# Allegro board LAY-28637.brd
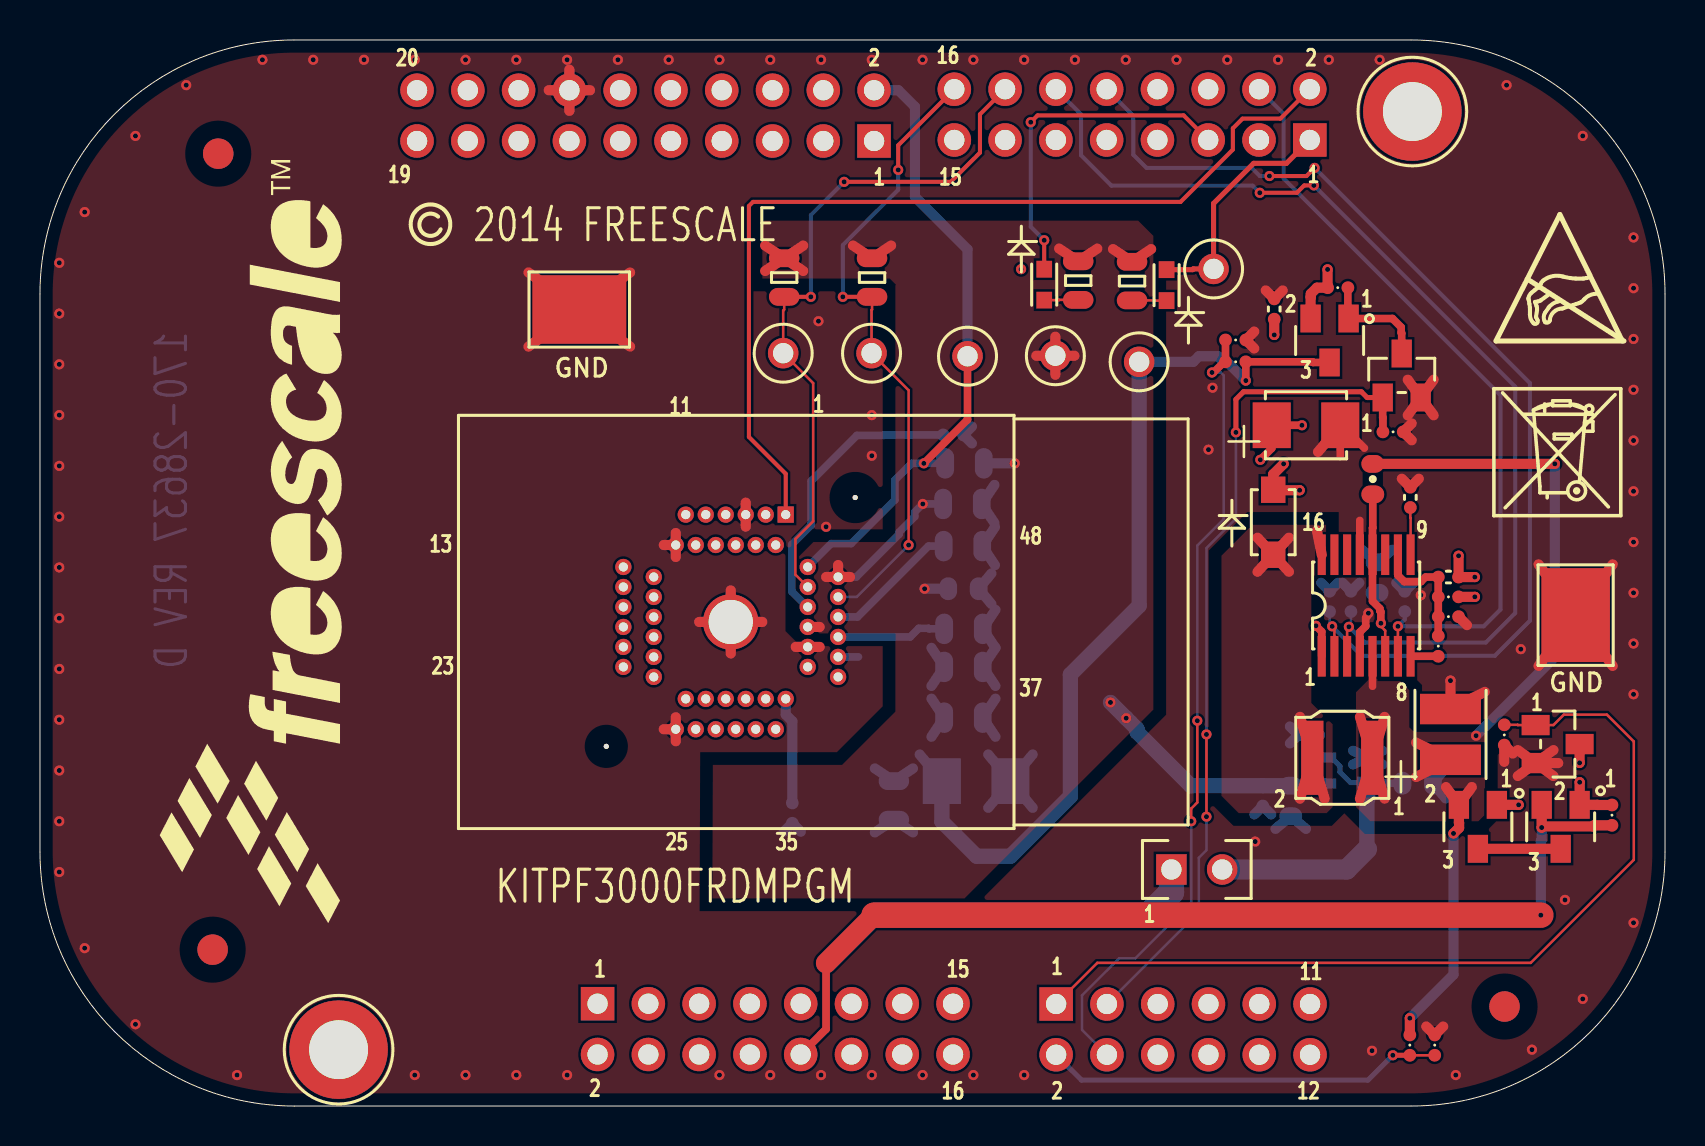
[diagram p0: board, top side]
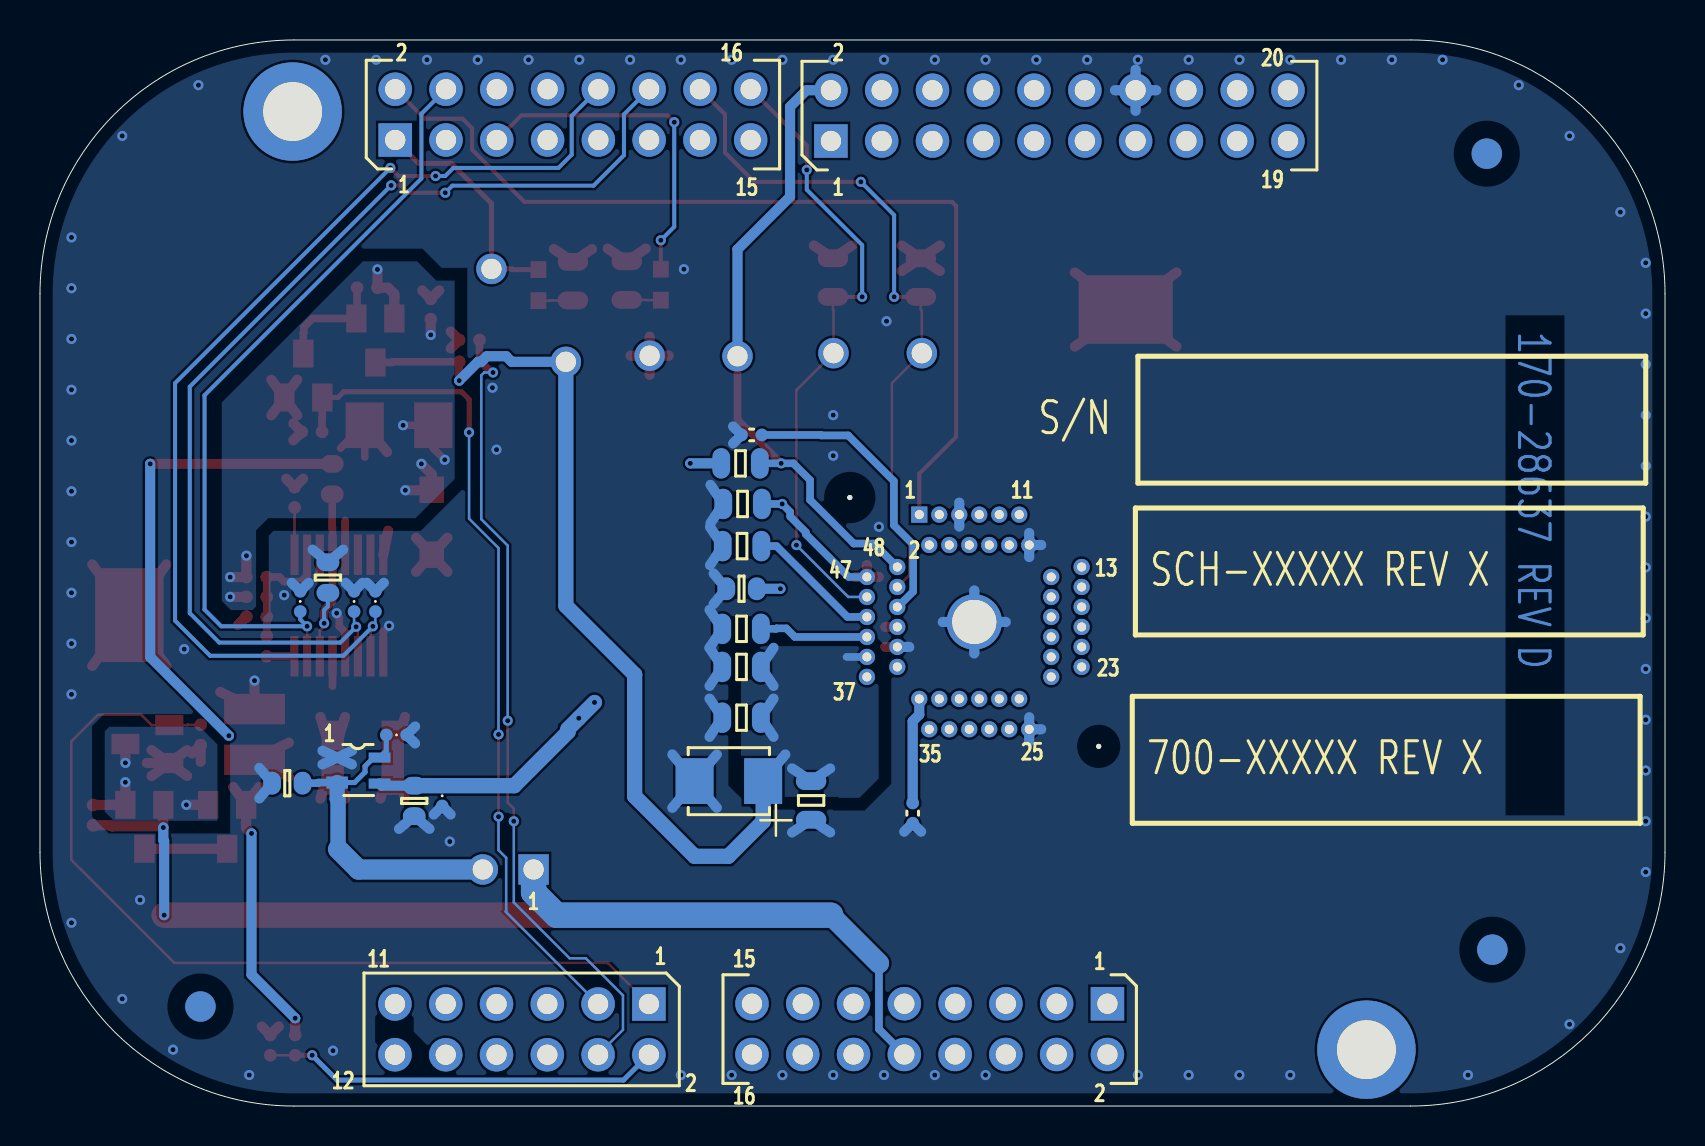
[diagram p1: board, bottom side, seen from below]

Outline 81.28 x 53.34 mm; copper layers: TOP, BOTTOM. Coordinates in mm from the lower left corner of the outline.
Outline path: 0,40.64 arc(3.72,49.62) 12.7,53.34 68.58,53.34 arc(77.56,49.62) 81.28,40.64 81.28,12.7 arc(77.56,3.72) 68.58,0 12.73,0 arc(3.74,3.72) 0,12.7 0,40.64

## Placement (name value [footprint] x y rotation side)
C1  0.1uF  [CC0402_25]  61.73 39.88 90 top
C2  4.7uF  [CC3528-21]  63.32 34.06 0 top
C3  0.1uF  [CC0402_25]  68.54 30.45 90 top
C4  22PF  [CC0402_25]  70.45 26.47 180 top
C5  15UF  [CASE_B]  70.55 18.59 90 top
C6  0.22uF  [CC0402_25]  45.68 33.58 0 bottom
C7  0.1UF  [CC0805_OV]  46.14 30.12 0 bottom
C8  1uF  [CC0805_OV]  46.16 28.02 0 bottom
C9  1.0UF  [CC0603_OV]  46.19 25.88 0 bottom
C10  1uF  [CC0805_OV]  46.19 23.88 0 bottom
C11  1UF  [CC0603_OV]  66.88 26.44 90 bottom
C12  10uF  [CC0805_OV]  46.19 21.97 0 bottom
C13  10uF  [CC3528-21]  46.82 16.26 0 bottom
C14  10uF  [CC0805_OV]  42.71 15.29 270 bottom
C15  0.22uF  [CC0402_25]  37.63 14.66 270 bottom
C16  1.0UF  [CC0603_OV]  62.56 15.27 270 bottom
C17  1.0UF  [CC0603_OV]  68.91 16.15 0 bottom
D1  LED Green  [LED_0603]  50.23 41.1 90 top
D2  LED Red  [LED_0603]  56.35 41.07 90 top
D3  MBR130LSFT1G  [SOD-123]  61.68 29.21 90 top
J1  HDR_2X8  [HDR208]  63.51 48.34 90 bottom
J2  HDR_10X2  [HDR210]  41.72 48.29 90 bottom
J3  HDR_2X8  [HDR208]  27.89 5.12 270 bottom
J4  HDR_2X6  [HDR206]  50.83 5.11 270 bottom
J9  HDR 1X2 TH  [HDR102]  56.59 11.84 90 top
L1  22uH  [IND2_4P3X4P3]  65.14 17.42 180 top
MH1  SMTSO-M1.6-2.25ET  [MH194-116T]  68.64 49.76 0 top
MH2  SMTSO-M1.6-2.25ET  [MH194-116T]  14.94 2.82 0 top
NOREF  -  [unnamed]  8.92 47.65 0 top
NOREF#2  -  [#2]  14.94 2.82 0 top
NOREF#3  -  [#2]  14.4 9.14 90 top
NOREF#4  -  [#2]  -403.54 -384.3 0 top
NOREF#5  -  [#2]  72.72 29.54 0 top
NOREF#6  -  [unnamed]  8.64 7.82 0 top
NOREF#7  -  [#2]  18.16 13.03 0 top
NOREF#8  -  [#2]  -5.22 -35.53 0 top
NOREF#9  -  [#2]  14.94 2.82 0 top
NOREF#10  -  [#2]  -377.51 140.84 0 top
NOREF#11  -  [#2]  19.66 44.25 0 top
NOREF#12  -  [#2]  14.94 2.82 0 top
NOREF#13  -  [#2]  78.26 48.87 0 top
NOREF#14  -  [#2]  0 40.64 0 top
NOREF#15  -  [#2]  132.25 57.23 0 top
NOREF#16  -  [#2]  -5.87 -51.31 0 top
NOREF#17  -  [#2]  72.85 38.28 0 top
NOREF#18  -  [unnamed]  73.25 4.98 0 top
NOREF#19  -  [#2]  68.58 0 90 top
NOREF#20  -  [unnamed]  8.92 47.65 180 bottom
NOREF#21  -  [unnamed]  73.25 4.98 180 bottom
NOREF#22  -  [#2]  26.64 14.15 180 bottom
NOREF#23  -  [#2]  35.94 7.95 180 bottom
NOREF#24  -  [#2]  26.49 23.57 180 bottom
NOREF#25  -  [#2]  26.37 31.17 180 bottom
NOREF#26  -  [unnamed]  8.64 7.82 180 bottom
Q1  FDN360P  [SSOT3]  64.5 38.3 180 top
Q2  BSS138  [SOT-23]  68.11 36.55 0 top
Q3  BSS138  [SOT-23]  75.91 18.11 270 top
Q4  FDN360P  [SSOT3]  71.92 13.97 180 top
Q5  FDN360P  [SSOT3]  76.06 13.97 180 top
R1  4.7K  [RC0805_OV]  37.22 41.45 270 top
R2  4.7K  [RC0805_OV]  41.62 41.45 270 top
R3  300  [RC0805_OV]  51.93 41.3 270 top
R4  300  [RC0805_OV]  54.62 41.27 270 top
R5  470K  [RC0402_25]  64.91 40.94 0 top
R6  470  [RC0402_25]  59.8 38.33 0 top
R7  1.0K  [RC0402_25]  59.8 37.24 180 top
R8  47K  [RC0402_25]  67.68 33.73 0 top
R9  100  [RC0603_OV]  66.66 31.37 270 top
R10  604K  [RC0402_25]  70.45 25.48 180 top
R11  120K  [RC0402_25]  70.45 24.49 0 top
R12  374K  [RC0402_25]  69.94 23.01 90 top
R13  47K  [RC0402_25]  73.24 18.57 270 top
R14  470K  [RC0402_25]  78.63 14.55 90 top
R15  1.0K  [RC0402_25]  68.52 3.05 270 top
R16  1.0K  [RC0402_25]  69.76 3.05 90 top
R17  10.0K  [RC0805_OV]  46.24 32.16 180 bottom
R18  10K  [RC0402_25]  68.26 25.25 90 bottom
R19  10K  [RC0402_25]  65.57 25.25 90 bottom
R20  10K  [RC0402_25]  64.5 25.25 90 bottom
R21  10.0K  [RC0805_OV]  46.19 19.43 0 bottom
R22  10K  [RC0402_25]  61.16 15.52 270 bottom
R23  10K  [RC0402_25]  63.45 18.57 180 bottom
SKT1  48QN50S17070  [SKT48_0P5_20X20]  37.3 29.59 0 top
TP1  TEST POINT RED  [TEST_LOOP]  58.7 41.88 90 top
TP2  TEST POINT RED  [TEST_LOOP]  37.17 37.67 0 top
TP3  TEST POINT RED  [TEST_LOOP]  41.59 37.67 0 top
TP4  TEST POINT RED  [TEST_LOOP]  50.79 37.54 0 top
TP5  TEST POINT RED  [TEST_LOOP]  46.39 37.52 0 top
TP6  TEST POINT RED  [TEST_LOOP]  54.98 37.24 0 top
TP7  TESTLOOP  [TEST_PIN_TP107]  76.81 24.56 90 top
TP8  TESTLOOP  [TEST_PIN_TP107]  26.97 39.85 0 top
U1  MAX686  [QSOP16]  66.33 25.04 90 top
U2  NCP562  [SC82_4]  65.35 16.78 180 bottom

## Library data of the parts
C1 C3 C6 C15 = CAP_NP: tolerance: 10%
C2 C5 = CAP_POL: tolerance: 10%
C4 = CAP_NP: tolerance: 5%
C7-C12 C14 C16 C17 = CAP_NP
C13 = CAP_POL
D1 D2 = LED
D3 = DIODE_SCHTKY
J1 J3 = CONN_HDR_8X2
J2 = CONN_HDR_10X2
J4 = CONN_HDR_6X2
J9 = CONN_HDR_1X2
L1 = INDUCTOR: tolerance: 20%
MH1 MH2 = MOUNT_HOLE
Q1 Q4 Q5 = MOSFET_P
Q2 Q3 = MOSFET_N
R1-R4 R17 R21 = MOT_RES: tolerance: 1%
R5-R8 R13-R16 = RES
R9-R12 = RES: tolerance: 1%
R18-R20 R22 R23 = RES: tolerance: 5%
SKT1 = MC32PF300XEP_48P
TP1-TP6 = TESTLOOP
TP7 TP8 = TestLoop
U1 = MAX686
U2 = NCP562

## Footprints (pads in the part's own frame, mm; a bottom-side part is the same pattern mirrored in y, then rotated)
CASE_B
  rect 1.524x3.048 smd: 1(-1.27,0) 2(1.27,0)
CC0402_25
  round 0.635 smd: 1(-0.508,0) 2(0.508,0)
CC0603_OV
  oval 0.889x1.143 smd: 1(-0.762,0) 2(0.762,0)
CC0805_OV
  oval 0.889x1.524 smd: 1(-0.965,0) 2(0.965,0)
CC3528-21
  rect 1.905x2.286 smd: 1(-1.714,0) 2(1.714,0)
HDR102
  rect 1.524x1.524 hole 1.016: 1(0,0)
  round 1.524 hole 1.016: 2(0,-2.54)
HDR206
  rect 1.676x1.676 hole 1.016: 1(0,0)
  round 1.676 hole 1.016: 2(2.54,0) 3(0,-2.54) 4(2.54,-2.54) 5(0,-5.08) 6(2.54,-5.08) 7(0,-7.62) 8(2.54,-7.62) 9(0,-10.16) 10(2.54,-10.16) 11(0,-12.7) 12(2.54,-12.7)
HDR208
  rect 1.676x1.676 hole 1.016: 1(0,0)
  round 1.676 hole 1.016: 2(2.54,0) 3(0,-2.54) 4(2.54,-2.54) 5(0,-5.08) 6(2.54,-5.08) 7(0,-7.62) 8(2.54,-7.62) 9(0,-10.16) 10(2.54,-10.16) 11(0,-12.7) 12(2.54,-12.7) 13(0,-15.24) 14(2.54,-15.24) 15(0,-17.78) 16(2.54,-17.78)
HDR210
  rect 1.676x1.676 hole 1.016: 1(0,0)
  round 1.676 hole 1.016: 2(2.54,0) 3(0,-2.54) 4(2.54,-2.54) 5(0,-5.08) 6(2.54,-5.08) 7(0,-7.62) 8(2.54,-7.62) 9(0,-10.16) 10(2.54,-10.16) 11(0,-12.7) 12(2.54,-12.7) 13(0,-15.24) 14(2.54,-15.24) 15(0,-17.78) 16(2.54,-17.78) 17(0,-20.32) 18(2.54,-20.32) 19(0,-22.86) 20(2.54,-22.86)
IND2_4P3X4P3
  rect 1.118x3.708 smd: 1(-1.5,0) 2(1.5,0)
LED_0603
  rect 0.838x0.787 smd: A(-0.775,0) C(0.775,0)
MH194-116T
  round 4.928 hole 2.946: 1(0,0)
QSOP16
  rect 2.032x0.406 smd: 1(-2.54,2.223) 2(-2.54,1.587) 3(-2.54,0.953) 4(-2.54,0.318) 5(-2.54,-0.318) 6(-2.54,-0.953) 7(-2.54,-1.587) 8(-2.54,-2.223) 9(2.54,-2.223) 10(2.54,-1.587) 11(2.54,-0.953) 12(2.54,-0.318) 13(2.54,0.318) 14(2.54,0.953) 15(2.54,1.587) 16(2.54,2.223)
RC0402_25
  round 0.635 smd: 1(-0.508,0) 2(0.508,0)
RC0603_OV
  oval 0.889x1.143 smd: 1(-0.762,0) 2(0.762,0)
RC0805_OV
  oval 0.889x1.524 smd: 1(-0.965,0) 2(0.965,0)
SC82_4
  rect 1.092x0.508 smd: 1(-1.06,0.65) 3(1.06,-0.65) 4(1.06,0.65)
  rect 1.08x0.6 smd: 2(-1.06,-0.6)
SKT48_0P5_20X20
  round 0.254 hole 1.397 unplated: (-8.975,-11.595)
  round 0.254 hole 1.803 unplated: (3.475,0.855)
  rect 0.813x0.813 hole 0.457: 1(0,0)
  round 0.813 hole 0.457: 2(-0.5,-1.52) 3(-1,0) 4(-1.5,-1.52) 5(-2,0) 6(-2.5,-1.52) 7(-3,0) 8(-3.5,-1.52) 9(-4,0) 10(-4.5,-1.52) 11(-5,0) 12(-5.5,-1.52) 13(-8.12,-2.62) 14(-6.6,-3.12) 15(-8.12,-3.62) 16(-6.6,-4.12) 17(-8.12,-4.62) 18(-6.6,-5.12) 19(-8.12,-5.62) 20(-6.6,-6.12) 21(-8.12,-6.62) 22(-6.6,-7.12) 23(-8.12,-7.62) 24(-6.6,-8.12) 25(-5.5,-10.74) 26(-5,-9.22) 27(-4.5,-10.74) 28(-4,-9.22) 29(-3.5,-10.74) 30(-3,-9.22) 31(-2.5,-10.74) 32(-2,-9.22) 33(-1.5,-10.74) 34(-1,-9.22) 35(-0.5,-10.74) 36(0,-9.22) 37(2.62,-8.12) 38(1.1,-7.62) 39(2.62,-7.12) 40(1.1,-6.62) 41(2.62,-6.12) 42(1.1,-5.62) 43(2.62,-5.12) 44(1.1,-4.62) 45(2.62,-4.12) 46(1.1,-3.62) 47(2.62,-3.12) 48(1.1,-2.62)
  round 2.769 hole 2.21: 49(-2.75,-5.37)
SOD-123
  rect 1.321x1.219 smd: A(-1.626,0) C(1.626,0)
SOT-23
  rect 1.016x1.397 smd: 1(-0.95,-1.1) 2(0.95,-1.1) 3(0,1.1)
SSOT3
  rect 1.016x1.397 smd: 1(-0.95,-1.1) 2(0.95,-1.1) 3(0,1.1)
TEST_LOOP
  round 1.524 hole 1.016: 1(0,0)
TEST_PIN_TP107
  rect 4.699x3.429 smd: 1(0,0)
unnamed
  round 1.524 smd: (0,0)

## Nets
3V3: C7.1 C9.1 C16.1 R1.1(A) R2.1(A) R3.1(A) R4.1(A) R17.1(A) R22.1 SKT1.42(VIN) SKT1.47(VDDIO) TP4.1(PIN1) U2.3(VOUT)
GNDREF2: SKT1.26(GNDREF2)
VDDOTP: C12.1 C13.1 C14.1 Q1.3(DRAIN) R7.1 R21.1(A) SKT1.39(VDDOTP) TP6.1(PIN1)
VDDOTP_SNS: J4.4(B2) R6.1 R7.2
VDDOTPEN: J4.3(A2) Q2.1(GATE) R8.1
0: C1.2 C2.2 C3.2 C5.2 C6.2 C7.2 C8.2 C9.2 C10.2 C11.2 C12.2 C13.2 C14.2 C15.2 C16.2 C17.2 J2.14 Q2.2(SOURCE) Q3.2(SOURCE) R6.2 R8.2 R11.2 R13.2 R16.2 R18.2 R19.2 R20.2 R21.2(B) R22.2 R23.2 SKT1.5(ICTEST) SKT1.12(GNDREF1) SKT1.25(VREFDDR) SKT1.40(GNDREF) SKT1.49(EPAD) TP7.1(PIN1) TP8.1(PIN1) U1.1(PGND) U1.4(POL) U1.13(GND) U2.1(GND)
BSTDN: J1.12(B6) R19.1 U1.3(DN)
BSTEN: J1.4(B2) R18.1 U1.7(S\H\D\N\)
BSTUP: J1.10(B5) R20.1 U1.2(UP)
GPIO1: D2.C(CATHODE) J1.1(A1) TP1.1(PIN1)
PMIC_INTB: J1.2(B1) SKT1.1(I\N\T\)
PTC3: D1.C(CATHODE) J1.5(A3)
PWRON: J2.2 R17.2(B) SKT1.48(PWRON) TP5.1(PIN1)
SCL: J1.14(B7) R1.2(B) SKT1.46(SCL) TP2.1(PIN1)
SDA: J1.16(B8) R2.2(B) SKT1.45(SDA) TP3.1(PIN1)
USB_IN: C5.1 L1.1 Q4.2(SOURCE) R9.1 R15.1 U1.5(VDD)
USB_PWR: J3.10(B5) J9.1(A1) Q5.2(SOURCE) R14.1
USB_SNS: J4.2(B1) R15.2 R16.1
VUSBEN: J4.1(A1) Q3.1(GATE) R13.1
N24449: D1.A(ANODE) R3.2(B)
N24709: D2.A(ANODE) R4.2(B)
N26623: Q3.3(DRAIN) Q4.1(GATE) Q5.1(GATE) R14.2
N26797: C1.1 C2.1 C4.1 D3.C Q1.2(SOURCE) R5.1 R10.1
N26859: C11.1 R9.2 U1.6(ISET) U1.12(VCC)
N27013: C3.1 U1.9(REF)
N27137: C4.2 R10.2 R11.1 R12.2 U1.10(FB)
N27169: D3.A L1.2 U1.16(LX)
N27367: Q1.1(GATE) Q2.3(DRAIN) R5.2
N40403: C15.1 SKT1.36(LICELL)
N42364: C10.1 SKT1.41(VCORE)
N42392: C8.1 SKT1.43(VCOREDIG)
N43199: C6.1 SKT1.44(VCOREREF)
N266411: Q4.3(DRAIN) Q5.3(DRAIN)
N383014: C17.1 J9.2(B1) R23.1 U2.2(VIN) U2.4(EN)
N2672513: R12.1 U1.8(DACOUT)

Pads without a net: J1 3 6 7 8 9 11 13 15; J2 1 3 4 5 6 7 8 9 10 11 12 13 15 16 17 18 19 20; J3 1 2 3 4 5 6 7 8 9 11 12 13 14 15 16; J4 5 6 7 8 9 10 11 12; MH1 1; MH2 1; SKT1 2 3 4 6 7 8 9 10 11 13 14 15 16 17 18 19 20 21 22 23 24 27 28 29 30 31 32 33 34 35 37 38; U1 11 14 15

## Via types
v1: diameter 0.508, hole 0.254, TOP to BOTTOM, 131 vias

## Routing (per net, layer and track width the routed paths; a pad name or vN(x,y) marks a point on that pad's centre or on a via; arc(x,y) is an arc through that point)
3V3: length 40
  TOP w0.508: SKT1.42 39,23.97 ; 50.98,42.9 R3.1 52.88,42.9 ; 39.32,26.47 SKT1.47 ; SKT1.47 39.92,27.07 ; SKT1.47 40.52,26.47 ; R1.1 38.18,43.05 ; R1.1 36.27,41.78 ; R1.1 38.18,41.78 ; R1.1 36.27,43.05 ; 40.66,43.05 R2.1 42.57,43.05 ; TP4.1 51.74,37.54 ; TP4.1 50.79,38.49 ; TP4.1 49.83,37.54 ; TP4.1 50.79,36.59 ; 55.58,42.88 R4.1 53.67,42.88
  BOTTOM w0.381: SKT1.47 40.83,26.47 42.98,28.62 42.98,28.71 43.75,29.49 43.75,29.72 v1(44.16,30.12) C7.1
  BOTTOM w0.508: C9.1 v1(44.25,25.88) ; R17.1 v1(48.76,32.16) ; U2.3 64.19,16.03 C16.1
  BOTTOM w0.762: C16.1 R22.1 57.56,16.03 54.87,18.71 54.87,18.87 v1(54.33,19.41) v1(53.54,20.19)
VDDOTP: length 54.3
  TOP w0.381: v1(60.31,36.3) R7.1 63.64,37.24 63.68,37.2 Q1.3
  BOTTOM w0.381: SKT1.39 40.94,22.47
  BOTTOM w0.508: 44.59,21.02 C12.1 44.59,22.92 ; TP6.1 57.68,37.24 57.96,37.52 58.93,37.52 59.21,37.24 59.37,37.24 v1(60.31,36.3) ; 43.66,16.89 C14.1 41.76,16.89 ; 44.59,18.48 R21.1 44.59,20.38 ; 44,17.59 C13.1
  BOTTOM w0.762: TP6.1 54.98,25.03 51.54,21.59 51.54,15.49 48.54,12.5 46.85,12.5 45.11,14.24 C13.1
VDDOTP_SNS: length 40.6
  TOP w0.127: v1(57.58,14.25) 57.58,14.88 57.89,15.19 v1(57.89,19.28)
  TOP w0.381: R6.1 R7.2 59.23,37.24 58.7,36.7 v1(58.62,36.7)
  BOTTOM w0.127: v1(57.89,19.28) 57.89,28.04 59.21,29.36 59.21,36.56 59.06,36.7 v1(58.62,36.7) ; v1(57.58,14.25) 57.58,10.19 54.79,7.39 53.98,7.39 52.12,5.54 52.12,3.81 J4.4
VDDOTPEN: length 42.3
  TOP w0.127: v1(58.34,18.59) v1(58.34,14.48)
  TOP w0.254: Q2.1 66.38,35.45 66.09,35.74 60.2,35.74 59.82,35.36 v1(59.82,33.71)
  TOP w0.381: Q2.1 67.16,34.43 67.17,34.42 R8.1
  BOTTOM w0.127: v1(59.82,33.71) 59.82,29.39 58.34,27.91 v1(58.34,18.59) ; v1(58.34,14.48) 58.34,12.8 57.96,12.42 57.96,9.75 57.99,9.73 J4.3
0: length 129.6
  TOP w0.381: U1.13 66.01,29.3 ; 66.24,32.92 65.1,34.06 C2.2 65.04,32.47 ; 64.11,22.5 64.11,23.74 v1(63.82,24.03) ; 66.01,22.5 66.01,23.71 66.31,24.01 66.31,24.43 66.41,24.53 66.41,24.63 v1(66.44,24.66)
  TOP w0.508: TP8.1 29.52,38 ; TP8.1 24.43,38 ; TP8.1 29.52,41.71 ; TP8.1 24.43,41.71 ; 69.34,3.98 R16.2 70.18,3.98 ; TP7.1 78.66,22.02 ; TP7.1 74.96,22.02 ; TP7.1 74.96,27.1 ; TP7.1 78.66,27.1 ; 61.31,40.81 C1.2 62.16,40.81 ; J2.14 26.48,51.85 ; J2.14 26.48,49.8 ; J2.14 27.51,50.83 ; J2.14 25.45,50.83 ; 73.92,16.51 Q3.2 ; Q3.2 73.92,17.81 ; Q3.2 75.7,17.81 ; Q3.2 75.7,16.51 ; Q3.2 75.94,17.16 ; 68.97,31.39 C3.2 68.12,31.39 ; 39,22.97 SKT1.40 37.8,22.97 ; SKT1.12 31.8,28.67 ; SKT1.12 31.8,27.47 ; SKT1.12 31.2,28.07 ; 72.26,20.72 C5.2 v1(70.55,21.29) ; 31.8,18.25 SKT1.25 ; SKT1.25 31.2,18.85 ; SKT1.25 31.8,19.45 ; Q2.2 69.71,36.34 ; Q2.2 69.71,34.56 ; Q2.2 68.41,36.34 ; Q2.2 68.41,34.56 ; 68.61,33.31 R8.2 68.61,34.15 ; 73.66,17.64 R13.2 73.24,17.22 ; SKT1.49 36.13,24.22 ; SKT1.49 34.55,22.65 ; SKT1.49 34.55,25.8 ; SKT1.49 32.97,24.22 ; 35.3,30.19 SKT1.5 35.3,28.99 ; 60.74,37.91 R6.2 60.74,38.75 ; 63.92,32.73 C2.2 ; R11.2 71.38,24.06
  BOTTOM w0.508: 47.43,14.92 C13.2 ; C13.2 49.65,17.59 ; C13.2 49.65,14.92 ; C13.2 47.43,17.59 ; 31.8,27.47 SKT1.12 ; SKT1.12 31.2,28.07 ; SKT1.12 31.8,28.67 ; 61.59,14.59 R22.2 60.74,14.59 ; 67.64,27.84 C11.2 66.12,27.84 ; 47.74,31.08 C7.2 47.74,29.17 ; 37.8,22.97 SKT1.40 ; 47.77,28.97 C8.2 47.77,27.06 ; 46.61,34 C6.2 46.61,33.16 ; SKT1.25 31.8,19.45 ; SKT1.25 31.2,18.85 ; SKT1.25 31.8,18.25 ; SKT1.49 34.55,25.8 ; SKT1.49 34.55,22.65 ; SKT1.49 32.97,24.22 ; SKT1.49 36.13,24.22 ; 47.79,21.02 C12.2 47.79,22.92 C10.2 47.79,24.83 ; U2.1 67.15,17.09 ; U2.1 65.68,17.09 ; U2.1 67.15,17.78 ; U2.1 65.68,17.78 ; J2.14 27.51,50.83 ; J2.14 25.45,50.83 ; J2.14 26.48,51.85 ; J2.14 26.48,49.8 ; 62.52,18.14 R23.2 62.52,18.99 ; 65.99,26.18 R19.2 65.15,26.18 ; 64.08,26.18 R20.2 64.93,26.18 ; 68.69,26.18 R18.2 67.84,26.18 ; 35.3,30.19 SKT1.5 35.3,28.99 ; 37.21,13.72 C15.2 38.05,13.72 ; 61.8,13.87 C16.2 63.32,13.87 ; 43.66,13.69 C14.2 41.76,13.69 ; 47.79,20.38 R21.2 47.79,18.48 ; 47.59,26.65 C9.2 47.59,25.12 ; 70.31,16.92 C17.2 70.31,15.39
  vias: v1(0.97,42.19) v1(0.97,39.65) v1(0.97,37.11) v1(0.97,34.57) v1(0.97,32.03) v1(0.97,29.49) v1(0.97,26.95) v1(0.97,24.41) v1(0.97,21.87) v1(0.97,19.33) v1(0.97,16.79) v1(0.97,14.25) v1(0.97,11.71) v1(2.24,44.73) v1(2.24,7.9) v1(4.78,48.54) v1(4.78,4.09) v1(7.32,51.08) v1(9.86,1.55) v1(11.13,52.35) v1(13.67,52.35) v1(16.21,52.35) v1(18.75,52.35) v1(18.75,1.55) v1(21.29,52.35) v1(21.29,1.55) v1(23.83,52.35) v1(23.83,1.55) v1(26.37,52.35) v1(26.37,1.55) v1(28.91,52.35) v1(31.45,52.35) v1(33.99,52.35) v1(33.99,1.55) v1(36.53,52.35) v1(36.53,1.55) v1(38.94,39.27) v1(39.07,52.35) v1(39.07,1.55) v1(39.32,28.98) v1(41.61,52.35) v1(41.61,34.57) v1(41.61,32.54) v1(41.61,1.55) v1(44.15,52.35) v1(44.15,1.55) v1(46.69,52.35) v1(46.69,1.55) v1(49.07,41.87) v1(49.23,52.35) v1(49.23,1.55) v1(51.77,52.35) v1(54.31,52.35) v1(56.85,52.35) v1(58.45,32.84) v1(58.65,35.94) v1(59.39,52.35) v1(60.78,13.23) v1(61.93,52.35) v1(64.47,52.35) v1(66.62,2.77) v1(67.01,52.35) v1(69.07,25.56) v1(70.82,1.55) v1(73.36,51.08) v1(74.07,22.86) v1(74.63,2.82) v1(76.28,10.31) v1(77.17,48.54) v1(77.17,5.36) v1(79.71,43.46) v1(79.71,40.92) v1(79.71,38.38) v1(79.71,35.84) v1(79.71,33.3) v1(79.71,30.76) v1(79.71,28.22) v1(79.71,25.68) v1(79.71,23.14) v1(79.71,20.6) v1(79.71,9.17)
BSTDN: length 53.5
  TOP w0.127: 65.38,22.5 65.38,23.81 65.47,23.9 v1(65.47,23.98)
  TOP w0.203: v1(61.01,45.69) 62.87,45.69 63.23,46.06 v1(63.72,46.06)
  BOTTOM w0.127: v1(65.47,23.98) 65.57,24.08 R19.1
  BOTTOM w0.203: v1(63.72,46.06) 73.79,35.99 73.79,24.66 72.31,23.19 66.26,23.19 v1(65.47,23.98) ; J1.12 52.07,49.62 52.07,47.57 53.59,46.05 60.66,46.05 v1(61.01,45.69)
BSTEN: length 38.9
  TOP w0.127: 67.92,22.5 v1(67.92,24)
  BOTTOM w0.203: J1.4 62.2,49.64 62.2,46.41 73.05,35.56 73.05,24.84 72.21,24 v1(67.92,24) 68.26,24.35 R18.1
BSTUP: length 54.2
  TOP w0.127: 64.74,22.5 64.74,23.89 64.63,24 v1(64.63,24)
  TOP w0.203: v1(61.49,46.53) 63.35,46.53 v1(63.75,46.94)
  BOTTOM w0.127: R20.1 64.5,24.16 64.63,24.03 v1(64.63,24)
  BOTTOM w0.203: v1(61.49,46.53) 61.01,46.53 60.6,46.94 55.35,46.94 54.69,47.6 54.69,49.54 J1.10 ; v1(63.75,46.94) 74.52,36.17 74.52,24.28 72.77,22.53 66.1,22.53 v1(64.63,24)
GPIO1: length 11.8
  TOP w0.254: D2.C 57.65,41.85 57.68,41.88 TP1.1 58.7,45.16 60.71,47.17 62.34,47.17 J1.1
PMIC_INTB: length 47.3
  TOP w0.203: SKT1.1 37.3,31.64 35.46,33.48 35.46,45.03 35.66,45.24 57.05,45.24 59.66,47.85 59.66,48.92 60.15,49.4 62.04,49.4 J1.2
PTC3: length 17.2
  TOP w0.203: D1.C v1(50.23,43.32) ; v1(49.56,49.23) 49.9,49.57 57.2,49.57 J1.5
  BOTTOM w0.203: v1(49.56,49.23) 49.56,43.99 v1(50.23,43.32)
PWRON: length 31.8
  TOP w0.381: v1(44.21,32.16) 46.39,34.34 TP5.1
  BOTTOM w0.381: SKT1.48 39.57,28.14 40.58,28.14 42.76,30.33 42.76,31.32 43.6,32.16 v1(44.21,32.16) R17.2
  BOTTOM w0.508: J2.2 42.94,50.83 43.76,50 43.76,45.49 46.39,42.86 TP5.1
SCL: length 34.7
  TOP w0.127: R1.2 37.22,39.85 37.17,39.8 TP2.1 38.67,36.17 38.67,29.26 37.78,28.37 37.78,26.59 SKT1.46
  TOP w0.203: R1.2 v1(38.56,40.49) ; v1(40.22,46.24) 45.55,46.24 47.02,47.7 47.02,49.62 J1.14
  BOTTOM w0.203: v1(38.56,40.49) 38.56,44.58 v1(40.22,46.24)
SDA: length 32
  TOP w0.127: v1(43.45,28.07) 43.45,35.81 TP3.1 41.59,39.83 41.62,39.85 R2.2
  TOP w0.203: v1(42.93,46.84) 42.93,48.07 J1.16 ; R2.2 v1(40.16,40.49)
  BOTTOM w0.127: SKT1.45 40.85,25.47 v1(43.45,28.07)
  BOTTOM w0.203: v1(40.16,40.49) 40.16,43.08 42.93,45.85 v1(42.93,46.84)
USB_IN: length 53
  TOP w0.381: 66.65,22.5 66.65,21.01
  TOP w0.508: R15.1 v1(68.52,4.39) ; Q4.2 71.62,15.96 ; Q4.2 70.32,15.96 ; Q4.2 70.97,14.18 70.98,14.17 70.98,13.92 v1(70.7,13.64) ; 68.83,18.18 C5.1 68.83,16.47 ; 66.02,19.47 L1.1 ; L1.1 67.25,15.38 ; L1.1 67.25,19.47 ; L1.1 66.02,15.38 ; R9.1 v1(75.77,32.13)
  BOTTOM w0.508: v1(71.83,18.53) 75.77,22.47 v1(75.77,32.13) ; v1(70.7,13.64) 70.7,6.58 v1(68.52,4.39)
USB_PWR: length 75.9
  TOP w0.381: 39.32,7.15 39.32,3.85 J3.10
  TOP w0.508: Q5.2 v1(75.11,13.93) 75.17,13.99 77.68,13.99 77.73,14.05 R14.1
  TOP w1.016: 39.32,7.15 41.72,9.55
  TOP w1.27: 41.72,9.55 v1(75.07,9.55)
  BOTTOM w0.381: J3.10 39.32,3.85 39.32,7.14
  BOTTOM w0.508: v1(75.07,9.55) 75.07,13.26 75.11,13.3 v1(75.11,13.93)
  BOTTOM w1.016: 39.32,7.14 41.73,9.55
  BOTTOM w1.27: 41.73,9.55 55.45,9.55 56.59,10.69 J9.1
USB_SNS: length 20
  TOP w0.127: R15.2 R16.1
  TOP w0.254: v1(67.67,2.54) R15.2
  BOTTOM w0.254: v1(67.67,2.54) 66.42,1.3 52.1,1.3 J4.2
VUSBEN: length 45.1
  TOP w0.127: R13.1 73.9,19.08 73.92,19.06 Q3.1 75.7,19.06 76.22,19.58 78.37,19.58 79.72,18.24 79.72,12.32 74.56,7.16 52.88,7.16 J4.1
N24449: length 1.7
  TOP w0.127: D1.A 50.96,40.32 50.98,40.34 R3.2
N24709: length 1.7
  TOP w0.127: R4.2 55.75,40.31 55.77,40.3 D2.A
N26623: length 4.8
  TOP w0.508: Q3.3 v1(77.01,17.17) ; R14.2 77.91,15.06 77.9,15.07 Q5.1 v1(77.01,16.2) ; Q4.1 v1(73.96,15.07)
N26797: length 12.9
  TOP w0.381: v1(61.04,32.33) 61.61,32.91 C2.1 v1(63.12,34.06)
  TOP w0.508: C1.1 v1(61.73,38.58) ; Q1.2 63.55,40.48 63.56,40.49 63.56,40.64 63.87,40.94 R5.1 v1(64.4,41.86) ; v1(63,30.81) 61.71,30.81 D3.C 61.68,31.61 v1(62.2,32.13) ; v1(70.95,27.53) C4.1 v1(71.77,26.47) ; R10.1 v1(71.77,25.48)
N26859: length 10
  TOP w0.127: v1(67.07,24.16) 67.07,24 67.28,23.79 67.28,22.5
  TOP w0.381: R9.2 66.66,28.93 66.65,28.92 U1.12 66.65,25.26 67.01,24.9 67.01,24.78 67.07,24.73 v1(67.07,24.16)
  BOTTOM w0.203: C11.1 66.88,25.01 67.07,24.82 v1(67.07,24.16)
N27013: length 2.4
  TOP w0.127: C3.1 68.54,29.44 68.55,29.43 U1.9
N27137: length 6.2
  TOP w0.381: R12.2 R11.1 R10.2 C4.2 69.3,26.47 69.08,26.24 68.23,26.24 67.92,26.55 U1.10
N27169: length 12.3
  TOP w0.508: D3.A 62.47,28.44 ; D3.A 62.47,26.73 ; D3.A 60.9,26.73 ; D3.A 60.9,28.44 ; L1.2 64.25,15.38 ; L1.2 63.02,15.38 ; L1.2 63.02,19.47 ; 63.87,28.79 U1.16
N27367: length 5.7
  TOP w0.381: Q2.3 68.11,38.67 68.08,38.69 68.08,38.96 67.65,39.4 Q1.1 65.42,39.44 R5.2
N40403: length 5.3
  BOTTOM w0.508: SKT1.36 37.3,19.58 37.63,19.25 C15.1
N42364: length 5.5
  BOTTOM w0.381: SKT1.41 43.52,23.47 43.95,23.9 44.44,23.9 44.46,23.88 C10.1
N42392: length 6.7
  BOTTOM w0.381: SKT1.43 40.89,24.47 44.44,28.02 C8.1
N43199: length 14.6
  BOTTOM w0.381: SKT1.44 38.38,24.97 37.6,25.74 37.6,28.09 38.57,29.06 38.57,31.27 40.86,33.55 42.2,33.55 42.23,33.58 C6.1
N266411: length 4.1
  TOP w0.508: Q5.3 Q4.3
N383014: length 16.8
  BOTTOM w0.254: R23.1 63.96,17.77 U2.4 64.59,17.43 65.02,17 65.02,16.71 65.54,16.18 U2.2
  BOTTOM w0.381: C17.1 67.39,16.15 67.36,16.18 U2.2
  BOTTOM w0.762: 66.37,12.85 66.37,15.33 66.41,15.38 U2.2
  BOTTOM w1.016: J9.2 65.35,11.84 66.37,12.85
N2672513: length 1.4
  TOP w0.381: 68.55,22.5 69.94,22.5

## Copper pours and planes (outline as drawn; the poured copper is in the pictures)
3V3 on TOP: 33.63,10.39 33.66,17.07 40.12,17.07 42.79,19.74 42.79,23.65 38.3,23.65 37.92,24.03 37.92,27.46 38.68,28.22 42.79,28.22 42.79,41.07 42.81,41.1 42.51,41.4 36.13,41.4 36.13,44.3 54.93,44.3 55.69,43.54 55.69,19.84 46.24,10.39 34.17,10.39 34.17,10.39
VDDOTP on BOTTOM: 41.36,15.47 45.38,15.47 46.22,16.31 46.22,22.23 45.43,23.01 39.89,23.01 39.33,22.45 39.33,16.38 40.3,15.42 41.31,15.42
0 on TOP: 12.73,0.63 4.18,4.17 0.63,12.7 0.63,40.64 4.17,49.17 12.7,52.7 68.58,52.7 77.11,49.17 80.64,40.64 80.64,12.7 77.11,4.17 68.58,0.63 ; 5 cut-outs
0 on BOTTOM: 12.73,0.63 4.18,4.17 0.63,12.7 0.63,40.64 4.17,49.17 12.7,52.7 68.58,52.7 77.11,49.17 80.64,40.64 80.64,12.7 77.11,4.17 68.58,0.63 ; 8 cut-outs
USB_IN on TOP: 66.46,23.57 66.46,21.34 65.82,20.7 65.82,14.96 66.54,14.25 71.95,14.25 72.28,14.58 72.28,18.64 72.2,18.72 68.72,18.72 68.49,18.95 68.49,20.8 68.03,21.26 66.92,21.26 66.89,21.29 66.89,23.57
N26623 on BOTTOM: 72.4,14.27 77.58,14.27 78.04,14.73 78.04,18.75 77.81,18.97 73.29,18.97 72.4,18.08
N26797 on BOTTOM: 70.65,24.82 71.73,24.82 72.19,25.27 72.19,35.2 65.13,42.27 62.42,42.27 61.46,41.3 60.54,41.3 60.54,31.37 62.5,29.41 69.86,29.41 70.47,28.8 70.47,24.99
N27169 on TOP: 64.35,14.66 59.96,14.66 59.09,15.52 59.09,27.53 60.64,29.08 64.33,29.08 64.33,26.54 63.59,26.54 63.59,20.17 64.66,19.1 64.66,14.96

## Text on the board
BOTTOM: 5 OF 8 | SECONDARY SIDE | 170-28637 REV D
Board Geometry/Soldermask Bottom: 6 OF 8 | SECONDARY SOLDERMASK
Ref Des/Silkscreen Bottom: 7 OF 8 | SECONDARY SILKSCREEN
User.Comments: 1 OF 1 | TEST PROBE | 1/1 | 1
TOP: 4 OF 8 | PRIMARY SIDE
Board Geometry/Soldermask Top: 3 OF 8 | PRIMARY SOLDERMASK
Ref Des/Silkscreen Top: GND | 2 OF 8 | PRIMARY SILKSCREEN | KITPF3000FRDMPGM
DIMENSION: PRIMARY DATUM | GRID ORIGIN
BODY_CENTER: 16 | 17 | 8
PASTEMASK_TOP: 1 OF 8 | PASTEMASK TOP
User.5: 8 OF 8 | SECONDARY PASTEMASK
User.13: 02-04-15 | 04-09-15 | 04-21-15 | A.G. | B | C | D | Refer to SCH-28637_B | Refer to SCH-28637_C | Refer to SCH-28637_D
User.18: FIGURE | SIZE | 10.0 | 18.0 | 40.0 | 87.0 | 116.0 | 55.0 | 71.0 | DRILL CHART: TOP to BOTTOM | ALL UNITS ARE IN MILS | TOLERANCE | +0.0/-10.0 | +2.0/-2.0 | +3.0/-3.0 | +3.15/-0.0 | PLATED | NON-PLATED | QTY | 131 | 48 | 72 | 1 | 2
